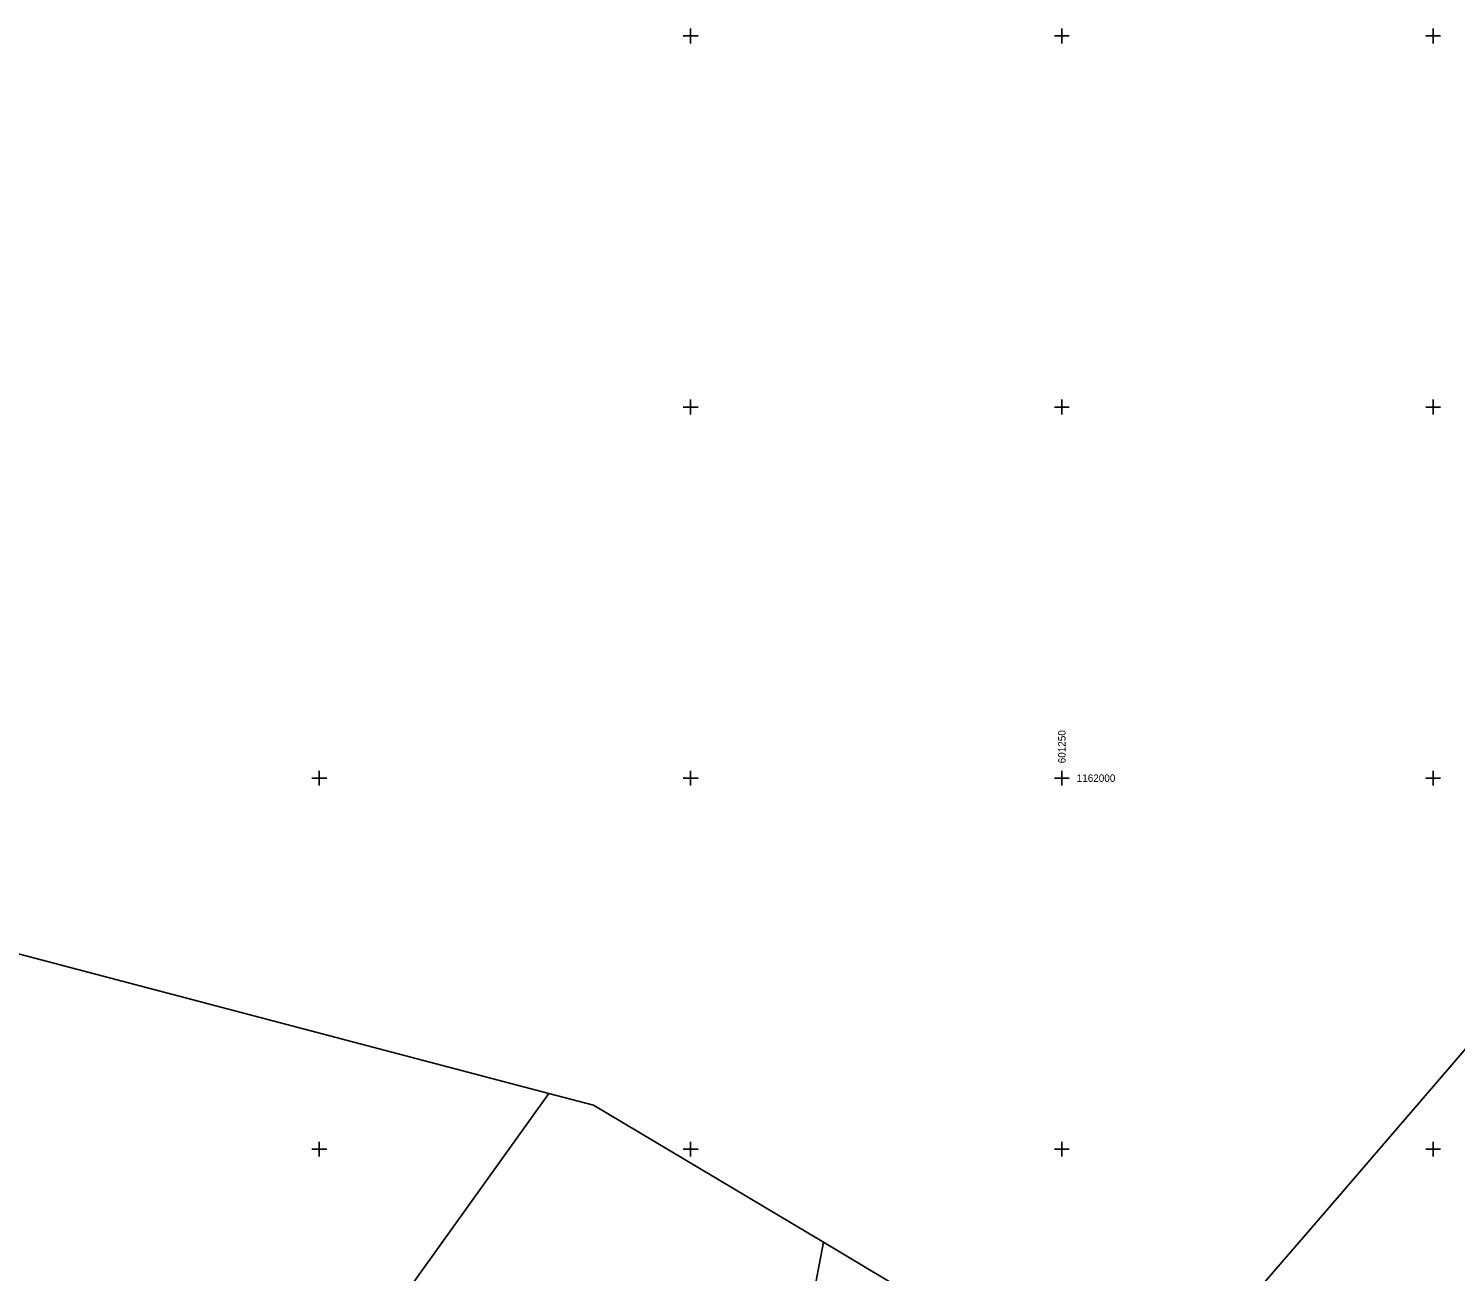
# Model space of a CAD drawing. Extents: x -601602 to -600882, y -1162594 to -1161950.
# Drawn here: x -601319.6 to -601223.5, y -1162033.2 to -1161949.5 of the extents above; entities that cross this region are included whole.
import ezdxf

# ---------------------------------------------------------------- set-up
doc = ezdxf.new("R2010")
doc.units = 0
doc.layers.add('KN_Hranice parcel', color=7, linetype='Continuous')
doc.layers.add('X_SOUR_KRIZKY_SEVER', color=7, linetype='Continuous')

msp = doc.modelspace()

# ---------------------------------------------------------------- linework, layer by layer
at = {"layer": 'KN_Hranice parcel'}
for p, q in [((-601284.54, -1162021.25), (-601352.14, -1162003.46)), ((-601284.54, -1162021.25), (-601281.53, -1162022.04)), ((-601281.53, -1162022.04), (-601266.06, -1162031.27)), ((-601232.03, -1162028.94), (-601244.21, -1162043.08)), ((-601266.06, -1162031.27), (-601273.32, -1162069.31)), ((-601244.9, -1162043.88), (-601266.06, -1162031.27))]:
    msp.add_line(p, q, dxfattribs=at)
for points in [[(-601129.54, -1161979.66), (-601196.39, -1161987.52), (-601232.03, -1162028.94)], [(-601297.47, -1162044.8), (-601295.33, -1162036.3), (-601284.54, -1162021.25)]]:
    msp.add_lwpolyline(points, dxfattribs=at)
at = {"layer": 'X_SOUR_KRIZKY_SEVER'}
for p, q in [((-601275.5, -1161950), (-601274.5, -1161950)), ((-601275, -1161950.5), (-601275, -1161949.5)), ((-601250.5, -1161950), (-601249.5, -1161950)), ((-601250, -1161950.5), (-601250, -1161949.5)), ((-601225.5, -1161950), (-601224.5, -1161950)), ((-601225, -1161950.5), (-601225, -1161949.5)), ((-601275.5, -1161975), (-601274.5, -1161975)), ((-601275, -1161975.5), (-601275, -1161974.5)), ((-601250.5, -1161975), (-601249.5, -1161975)), ((-601250, -1161975.5), (-601250, -1161974.5)), ((-601225.5, -1161975), (-601224.5, -1161975)), ((-601225, -1161975.5), (-601225, -1161974.5)), ((-601300.5, -1162000), (-601299.5, -1162000)), ((-601300, -1162000.5), (-601300, -1161999.5)), ((-601275.5, -1162000), (-601274.5, -1162000)), ((-601275, -1162000.5), (-601275, -1161999.5)), ((-601250.5, -1162000), (-601249.5, -1162000)), ((-601250, -1162000.5), (-601250, -1161999.5)), ((-601225.5, -1162000), (-601224.5, -1162000)), ((-601225, -1162000.5), (-601225, -1161999.5)), ((-601300.5, -1162025), (-601299.5, -1162025)), ((-601300, -1162025.5), (-601300, -1162024.5)), ((-601275.5, -1162025), (-601274.5, -1162025)), ((-601275, -1162025.5), (-601275, -1162024.5)), ((-601250.5, -1162025), (-601249.5, -1162025)), ((-601250, -1162025.5), (-601250, -1162024.5)), ((-601225.5, -1162025), (-601224.5, -1162025)), ((-601225, -1162025.5), (-601225, -1162024.5))]:
    msp.add_line(p, q, dxfattribs=at)

# ---------------------------------------------------------------- texts
msp.add_text('601250', height=0.5, rotation=90, dxfattribs=at).set_placement((-601249.75, -1161999))
msp.add_text('1162000', height=0.5, dxfattribs=at).set_placement((-601249, -1162000.25))

doc.saveas('drawing.dxf')
